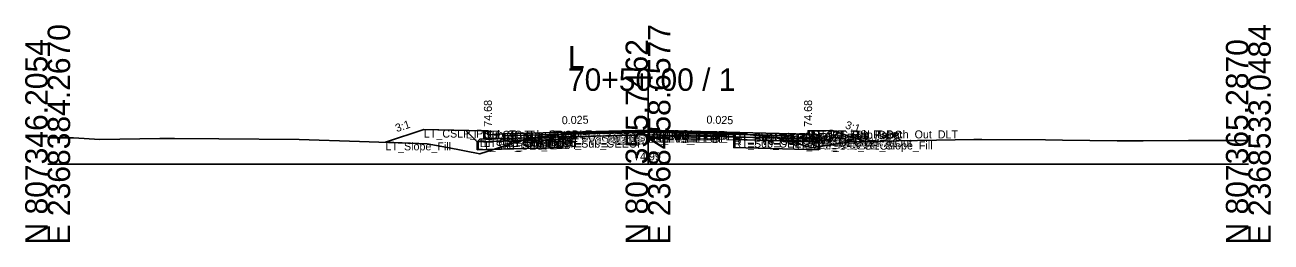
# Model space of a CAD drawing. Extents: x -26 to 8153, y -10 to 9520.
# Drawn here: x 6997.2 to 7152.8, y 990.3 to 1017.4 of the extents above; entities that cross this region are included whole.
import ezdxf

# ---------------------------------------------------------------- set-up
doc = ezdxf.new("R2010")
doc.units = 0
for name, color, linetype in [('Exist CMT Pavement', 7, 'Continuous'), ('Exist Cross Section Cell', 7, 'Continuous'), ('Exist XS Center Line Elevation Label', 7, 'Continuous'), ('Exist XS Ground Line', 7, 'Continuous'), ('Prop CMT Conc Surface', 7, 'Continuous'), ('Prop CMT Concrete Structures', 7, 'Continuous'), ('Prop CMT Pvmt Course 1', 7, 'Continuous'), ('Prop CMT Pvmt Course 1 CG', 7, 'Continuous'), ('Prop CMT Pvmt Course 1 Wedge', 7, 'Continuous'), ('Prop CMT Pvmt Course 2', 7, 'Continuous'), ('Prop CMT Pvmt Course 2 Wedge', 7, 'Continuous'), ('Prop CMT Pvmt Course 3', 7, 'Continuous'), ('Prop CMT Pvmt Course 3 Wedge', 7, 'Continuous'), ('Prop CMT Pvmt Surface', 7, 'Continuous'), ('Prop CMT Pvmt Wedge Surface 1', 7, 'Continuous'), ('Prop CMT Pvmt Wedge Surface 2', 7, 'Continuous'), ('Prop CMT Pvmt Wedge Surface 3', 7, 'Continuous'), ('Prop CMT Shallow Undercut', 7, 'Continuous'), ('Prop CMT Shallow Undercut Boundary', 7, 'Continuous'), ('Prop CMT Slope Grass', 7, 'Continuous'), ('Prop CMT Subgrade Earthwork', 7, 'Continuous'), ('Prop XS Earthwork Shape', 7, 'Continuous'), ('Prop XS Hydro Elevations', 7, 'Continuous'), ('Prop XS SE Text', 7, 'Continuous'), ('Prop XS Side Slope Text', 7, 'Continuous'), ('Prop XS Subgrade Earthwork', 7, 'Continuous'), ('Scratch_Level_2', 7, 'Continuous'), ('Scratch_Level_6', 7, 'Continuous')]:
    doc.layers.add(name, color=color, linetype=linetype)

msp = doc.modelspace()

# ---------------------------------------------------------------- linework, layer by layer
at = {"layer": 'Exist CMT Pavement'}
for p, q in [((7064.35, 1003.78), (7067.62, 1003.85)), ((7067.62, 1003.85), (7074.86, 1003.99)), ((7074.86, 1003.99), (7081.77, 1003.93)), ((7081.77, 1003.93), (7085.71, 1003.9))]:
    msp.add_line(p, q, dxfattribs=at)
at = {"layer": 'Exist Cross Section Cell'}
for p, q in [((7075, 1000), (7075, 1011.96)), ((7000, 1000), (7075, 1000)), ((7075, 1000), (7150, 1000))]:
    msp.add_line(p, q, dxfattribs=at)
at = {"layer": 'Exist XS Ground Line'}
for p, q in [((7000, 1003.31), (7003.21, 1003.28)), ((7003.21, 1003.28), (7006.51, 1003.11)), ((7006.51, 1003.11), (7014.02, 1003.23)), ((7014.02, 1003.23), (7015.86, 1003.23)), ((7015.86, 1003.23), (7021.38, 1003.18)), ((7021.38, 1003.18), (7031.4, 1003.08)), ((7031.4, 1003.08), (7038.94, 1002.84)), ((7038.94, 1002.84), (7047.41, 1002.57)), ((7057.13, 1002.29), (7059.75, 1003.14)), ((7059.75, 1003.14), (7060.62, 1003.26)), ((7060.62, 1003.26), (7064.35, 1003.78)), ((7064.35, 1003.78), (7067.62, 1003.85)), ((7067.62, 1003.85), (7074.86, 1003.99)), ((7074.86, 1003.99), (7081.77, 1003.93)), ((7081.77, 1003.93), (7085.71, 1003.9)), ((7085.71, 1003.9), (7089.8, 1003.48)), ((7089.8, 1003.48), (7090.7, 1003.38)), ((7090.7, 1003.38), (7094.98, 1002.2)), ((7098.84, 1002.59), (7100.39, 1002.82)), ((7100.39, 1002.82), (7104, 1002.88)), ((7104, 1002.88), (7115.72, 1003.09)), ((7115.72, 1003.09), (7116.69, 1003.09)), ((7116.69, 1003.09), (7124.66, 1003.04)), ((7124.66, 1003.04), (7126.77, 1003.02)), ((7126.77, 1003.02), (7133.6, 1002.94)), ((7133.6, 1002.94), (7136.85, 1002.94)), ((7136.85, 1002.94), (7142.53, 1002.96)), ((7142.53, 1002.96), (7146.94, 1002.95)), ((7146.94, 1002.95), (7150, 1002.96)), ((7047.41, 1002.57), (7049.93, 1002.11)), ((7049.93, 1002.11), (7053.99, 1001.29)), ((7053.99, 1001.29), (7057.13, 1002.29)), ((7094.98, 1002.2), (7095.45, 1002.06)), ((7095.45, 1002.06), (7098.84, 1002.59))]:
    msp.add_line(p, q, dxfattribs=at)
at = {"layer": 'Prop CMT Conc Surface'}
for points in [[(7055, 1003.68), (7055, 1004.18), (7054.5, 1004.18)], [(7095, 1003.68), (7095, 1004.18), (7095.5, 1004.18)], [(7057, 1003.81), (7055, 1003.68)], [(7093, 1003.81), (7095, 1003.68)]]:
    msp.add_lwpolyline(points, dxfattribs=at)
at = {"layer": 'Prop CMT Concrete Structures'}
for points in [[(7057, 1003.81), (7055, 1003.68), (7055, 1004.18), (7054.5, 1004.18)], [(7054.5, 1004.18), (7054.5, 1003.17), (7057, 1003.23)], [(7093, 1003.81), (7095, 1003.68), (7095, 1004.18), (7095.5, 1004.18)], [(7095.5, 1004.18), (7095.5, 1003.17), (7093, 1003.23)], [(7057, 1003.23), (7057, 1003.81)], [(7093, 1003.23), (7093, 1003.81)]]:
    msp.add_lwpolyline(points, dxfattribs=at)
at = {"layer": 'Prop CMT Pvmt Course 1'}
for points in [[(7075, 1004.26), (7057, 1003.81)], [(7075, 1004.01), (7075, 1004.26)], [(7075, 1004.26), (7093, 1003.81)], [(7075, 1004.01), (7075, 1004.26)], [(7057, 1003.81), (7057, 1003.56)], [(7057, 1003.56), (7064.35, 1003.75)], [(7064.35, 1003.87), (7075, 1004.14)], [(7064.35, 1003.75), (7064.35, 1003.87)], [(7075, 1004.14), (7075, 1004.01), (7075, 1004.01)], [(7085.71, 1003.87), (7075, 1004.14)], [(7075, 1004.14), (7075, 1004.01), (7075, 1004.01)], [(7085.71, 1003.75), (7085.71, 1003.87)], [(7093, 1003.56), (7085.71, 1003.75)], [(7093, 1003.81), (7093, 1003.56)]]:
    msp.add_lwpolyline(points, dxfattribs=at)
at = {"layer": 'Prop CMT Pvmt Course 1 CG'}
for points in [[(7057, 1003.23), (7054, 1003.15), (7053.66, 1002.82)], [(7053.66, 1002.82), (7057, 1002.9)], [(7057, 1002.9), (7057, 1003.23)], [(7093, 1003.23), (7096, 1003.15), (7096.34, 1002.82)], [(7093, 1002.9), (7093, 1003.23)], [(7096.34, 1002.82), (7093, 1002.9)]]:
    msp.add_lwpolyline(points, dxfattribs=at)
at = {"layer": 'Prop CMT Pvmt Course 1 Wedge'}
for points in [[(7075, 1004.14), (7064.35, 1003.87)], [(7075, 1004.14), (7085.71, 1003.87)]]:
    msp.add_lwpolyline(points, dxfattribs=at)
at = {"layer": 'Prop CMT Pvmt Course 2'}
for points in [[(7064.35, 1003.75), (7057, 1003.56)], [(7057, 1003.56), (7057, 1003.23)], [(7057, 1003.23), (7064.35, 1003.42)], [(7064.35, 1003.42), (7064.35, 1003.75)], [(7085.71, 1003.42), (7085.71, 1003.75)], [(7085.71, 1003.75), (7093, 1003.56)], [(7093, 1003.23), (7085.71, 1003.42)], [(7093, 1003.56), (7093, 1003.23)]]:
    msp.add_lwpolyline(points, dxfattribs=at)
at = {"layer": 'Prop CMT Pvmt Course 2 Wedge'}
for points in [[(7075, 1004.01), (7064.35, 1003.75)], [(7075, 1004.01), (7085.71, 1003.75)]]:
    msp.add_lwpolyline(points, dxfattribs=at)
at = {"layer": 'Prop CMT Pvmt Course 3'}
for points in [[(7064.35, 1003.42), (7057, 1003.23)], [(7057, 1003.23), (7057, 1002.9)], [(7057, 1002.9), (7064.35, 1003.08)], [(7064.35, 1003.08), (7064.35, 1003.42)], [(7085.71, 1003.42), (7093, 1003.23)], [(7085.71, 1003.08), (7085.71, 1003.42)], [(7093, 1002.9), (7085.71, 1003.08)], [(7093, 1003.23), (7093, 1002.9)]]:
    msp.add_lwpolyline(points, dxfattribs=at)
at = {"layer": 'Prop CMT Pvmt Course 3 Wedge'}
for points in [[(7075, 1003.68), (7064.35, 1003.42)], [(7075, 1003.68), (7085.71, 1003.42)]]:
    msp.add_lwpolyline(points, dxfattribs=at)
at = {"layer": 'Prop CMT Pvmt Surface'}
for points in [[(7075, 1004.26), (7057, 1003.81)], [(7075, 1004.26), (7093, 1003.81)]]:
    msp.add_lwpolyline(points, dxfattribs=at)
at = {"layer": 'Prop CMT Pvmt Wedge Surface 1'}
for points in [[(7057, 1003.56), (7057, 1003.81)], [(7064.35, 1003.75), (7057, 1003.56)], [(7075, 1004.14), (7064.35, 1003.87)], [(7064.35, 1003.87), (7064.35, 1003.75)], [(7075, 1004.14), (7085.71, 1003.87)], [(7085.71, 1003.87), (7085.71, 1003.75)], [(7085.71, 1003.75), (7093, 1003.56)], [(7093, 1003.56), (7093, 1003.81)]]:
    msp.add_lwpolyline(points, dxfattribs=at)
at = {"layer": 'Prop CMT Pvmt Wedge Surface 2'}
for points in [[(7075, 1004.01), (7057, 1003.56)], [(7057, 1003.56), (7057, 1003.81)], [(7075, 1004.01), (7093, 1003.56)], [(7093, 1003.56), (7093, 1003.81)]]:
    msp.add_lwpolyline(points, dxfattribs=at)
at = {"layer": 'Prop CMT Pvmt Wedge Surface 3'}
for points in [[(7057, 1003.23), (7057, 1003.81)], [(7075, 1003.68), (7057, 1003.23)], [(7075, 1003.68), (7093, 1003.23)], [(7093, 1003.23), (7093, 1003.81)]]:
    msp.add_lwpolyline(points, dxfattribs=at)
at = {"layer": 'Prop CMT Shallow Undercut'}
for points in [[(7057.13, 1002.29), (7059.17, 1002.95), (7064.35, 1003.08), (7064.35, 1002.08), (7055.82, 1001.87)], [(7095.45, 1002.06), (7096.34, 1002.2), (7096.34, 1001.82), (7085.71, 1002.08), (7085.71, 1003.08), (7092.39, 1002.91), (7094.98, 1002.2)]]:
    msp.add_lwpolyline(points, close=True, dxfattribs=at)
at = {"layer": 'Prop CMT Shallow Undercut Boundary'}
for p, q in [((7053.66, 1002.82), (7053.66, 1001.82)), ((7064.35, 1003.08), (7064.35, 1002.08)), ((7085.71, 1003.08), (7085.71, 1002.08)), ((7096.34, 1002.82), (7096.34, 1001.82)), ((7053.66, 1001.82), (7064.35, 1002.08)), ((7085.71, 1002.08), (7096.34, 1001.82))]:
    msp.add_line(p, q, dxfattribs=at)
at = {"layer": 'Prop CMT Slope Grass'}
for points in [[(7054.5, 1004.18), (7047, 1004.33), (7042.21, 1002.74)], [(7095.5, 1004.18), (7098, 1004.23), (7102.15, 1002.85)]]:
    msp.add_lwpolyline(points, dxfattribs=at)
at = {"layer": 'Prop CMT Subgrade Earthwork'}
for points in [[(7057, 1002.9), (7053.66, 1002.82), (7052.25, 1004.23)], [(7093, 1002.9), (7096.34, 1002.82), (7097.75, 1004.23)], [(7064.35, 1003.08), (7057, 1002.9)], [(7064.35, 1003.08), (7064.36, 1003.78)], [(7085.71, 1003.08), (7085.69, 1003.9)], [(7085.71, 1003.08), (7093, 1002.9)]]:
    msp.add_lwpolyline(points, dxfattribs=at)
at = {"layer": 'Prop XS Earthwork Shape'}
for points in [[(7053.66, 1001.82), (7055.82, 1001.87), (7053.99, 1001.29), (7049.93, 1002.11), (7047.41, 1002.57), (7042.21, 1002.74), (7047, 1004.33), (7052.25, 1004.23), (7053.66, 1002.82)], [(7096.34, 1002.82), (7096.34, 1002.2), (7098.84, 1002.59), (7100.39, 1002.82), (7102.15, 1002.85), (7098, 1004.23), (7097.75, 1004.23)], [(7053.66, 1001.82), (7055.82, 1001.87), (7057.13, 1002.29), (7059.17, 1002.95), (7057, 1002.9), (7053.66, 1002.82)], [(7057.13, 1002.29), (7059.17, 1002.95), (7064.35, 1003.08), (7064.35, 1002.08), (7055.82, 1001.87)], [(7059.75, 1003.14), (7060.62, 1003.26), (7064.35, 1003.78), (7064.36, 1003.78), (7064.35, 1003.08), (7059.17, 1002.95)], [(7085.71, 1003.08), (7085.69, 1003.9), (7085.71, 1003.9), (7089.8, 1003.48), (7090.7, 1003.38), (7092.39, 1002.91)], [(7085.71, 1002.08), (7096.34, 1001.82), (7096.34, 1002.2), (7095.45, 1002.06), (7094.98, 1002.2), (7092.39, 1002.91), (7085.71, 1003.08)], [(7096.34, 1002.82), (7096.34, 1002.2), (7095.45, 1002.06), (7094.98, 1002.2), (7092.39, 1002.91), (7093, 1002.9)]]:
    msp.add_lwpolyline(points, close=True, dxfattribs=at)
at = {"layer": 'Prop XS Subgrade Earthwork'}
for p, q in [((7053.66, 1002.82), (7064.35, 1003.08)), ((7085.71, 1003.08), (7096.34, 1002.82))]:
    msp.add_line(p, q, dxfattribs=at)
at = {"layer": 'Scratch_Level_6'}
for points in [[(7057.13, 1002.29), (7059.17, 1002.95), (7064.35, 1003.08), (7064.35, 1002.08), (7055.82, 1001.87)], [(7095.45, 1002.06), (7096.34, 1002.2), (7096.34, 1001.82), (7085.71, 1002.08), (7085.71, 1003.08), (7092.39, 1002.91), (7094.98, 1002.2)]]:
    msp.add_lwpolyline(points, close=True, dxfattribs=at)

# ---------------------------------------------------------------- texts
at = {"layer": 'Exist Cross Section Cell'}
for s, p in [('E 2368384.2670', (7002.8, 990)), ('E 2368458.6577', (7077.8, 990)), ('E 2368533.0484', (7152.8, 990)), ('N 807346.2054', (7000, 990)), ('N 807355.7462', (7075, 990)), ('N 807365.2870', (7150, 990))]:
    msp.add_text(s, height=2.8, rotation=90, dxfattribs=at).set_placement(p)
for s, p in [('L', (7065, 1011.96)), ('70+50.00 / 1', (7065, 1009.16))]:
    msp.add_text(s, height=2.8, dxfattribs=at).set_placement(p)
at = {"layer": 'Exist XS Center Line Elevation Label'}
msp.add_text('74.99', height=1, dxfattribs=at).set_placement((7073.26, 1000.49))
at = {"layer": 'Prop XS Hydro Elevations'}
for p in [(7055.5, 1004.68), (7095.5, 1004.68)]:
    msp.add_text('74.68', height=1, rotation=90, dxfattribs=at).set_placement(p)
at = {"layer": 'Prop XS SE Text'}
for rotation, p in [(1.4321, (7064.24, 1004.99)), (358.5679, (7082.29, 1005.08))]:
    msp.add_text('0.025', height=1, rotation=rotation, dxfattribs=at).set_placement(p)
at = {"layer": 'Prop XS Side Slope Text'}
for rotation, p in [(18.4349, (7043.62, 1004)), (341.5651, (7099.56, 1004.5))]:
    msp.add_text('3:1', height=1, rotation=rotation, dxfattribs=at).set_placement(p)
at = {"layer": 'Scratch_Level_2'}
for s, p in [('LT_CSLP_Pnt', (7047, 1003.33)), ('LT_Sub_Trench_Out_DLT', (7052.25, 1003.23)), ('LT_CG_Top_BOC', (7054.5, 1003.18)), ('LT_CG_Top_Face', (7055, 1003.18)), ('PV1_PGL', (7075, 1003.26)), ('RT_PV1_IEEOP', (7075, 1003.14)), ('LT_PV1_IEEOP', (7075, 1003.14)), ('RT_CG_Top_Face', (7095, 1003.18)), ('RT_CG_Top_BOC', (7095.5, 1003.18)), ('RT_Sub_Trench_Out_DLT', (7097.75, 1003.23)), ('RT_CSLP_Pnt', (7098, 1003.23)), ('LT_Slope_Fill', (7042.21, 1001.74)), ('LT_Sub_OEOP', (7053.66, 1001.82)), ('LT_CG1_Shelf_Out', (7054, 1002.15)), ('LT_CG_Bot_BOC', (7054.5, 1002.17)), ('LT_CG_Top_Gut', (7055, 1002.68)), ('LT_PV1_OEOT', (7057, 1002.81)), ('LT_PV2_OEOT', (7057, 1002.56)), ('LT_PV3_OEOT', (7057, 1002.23)), ('LT_CG_Bot_IE', (7057, 1002.23)), ('LT_Sub_OEOT', (7057, 1001.9)), ('LT_PV1_OEEOP', (7064.35, 1002.87)), ('LT_PV_OEEOP_EG', (7064.35, 1002.78)), ('LT_PV2_OEEOP', (7064.35, 1002.75)), ('LT_PV3_OEEOP', (7064.35, 1002.42)), ('LT_Sub_OEEOP', (7064.35, 1002.08)), ('LT_PV_Sub_Tie_Out', (7064.36, 1002.78)), ('RT_PV2_IEEOP', (7075, 1003.01)), ('LT_PV2_IEEOP', (7075, 1003.01)), ('PV2_PGL', (7075, 1003.01)), ('RT_PV_IEEOP_EG', (7075, 1002.99)), ('LT_PV_IEEOP_EG', (7075, 1002.99)), ('RT_PV3_IEEOP', (7075, 1002.68)), ('LT_PV3_IEEOP', (7075, 1002.68)), ('RT_PV_Sub_Tie_Out', (7085.69, 1002.9)), ('RT_PV_OEEOP_EG', (7085.71, 1002.9)), ('RT_PV1_OEEOP', (7085.71, 1002.87)), ('RT_PV2_OEEOP', (7085.71, 1002.75)), ('RT_PV3_OEEOP', (7085.71, 1002.42)), ('RT_Sub_OEEOP', (7085.71, 1002.08)), ('RT_PV1_OEOT', (7093, 1002.81)), ('RT_PV2_OEOT', (7093, 1002.56)), ('RT_PV3_OEOT', (7093, 1002.23)), ('RT_CG_Bot_IE', (7093, 1002.23)), ('RT_Sub_OEOT', (7093, 1001.9)), ('RT_CG_Top_Gut', (7095, 1002.68)), ('RT_CG_Bot_BOC', (7095.5, 1002.17)), ('RT_CG1_Shelf_Out', (7096, 1002.15)), ('RT_Sub_OEOP', (7096.34, 1001.82)), ('RT_Slope_Fill', (7102.15, 1001.85))]:
    msp.add_text(s, height=1, dxfattribs=at).set_placement(p)

doc.saveas('drawing.dxf')
